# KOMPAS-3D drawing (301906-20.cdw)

Views: Вид 1
Referenced files: лист 4-фланец.cdw
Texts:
  Фланец люка
  денис
  Текст на чертеже
  Размерные надписи
  Шероховатость
  Линия-выноска #1
  Линия-выноска #2
  Линия-выноска #3
  Отклонения формы и база
  Заголовок таблицы
  Ячейка таблицы
  Стрелка вида
  Обозначение изменения
  Фигурная скобка
  Номер узла
  Марка координационной оси
  VRCB
  Выносная надпись
  Обозначение узла
  Марка/позиционное обозначение с линией-выноской
  Марка/позиционное обозначение на линии
  Марка/позиционное обозначение без линии-выноски
  Ra 6,3
  1. Неуказанные предельные отклонения размеров валов h14,
  отверстий H14, остальных   IT 14/2
  Злобин Д.В.
  СПбГТИ(ТУ)
  гр.364
  Сталь X18H10T ГОСТ 5632-72
Dimensions and other numbers on the sheet: 7; 500; 514; 12; 543,33; 20,83; 12,5; 536,66; 600; 566,66; 2,5; 20 отв.; 23; 4; 0,004; 1:2; 1; 15; 0; 2; 3; 5; 6; 8; 9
